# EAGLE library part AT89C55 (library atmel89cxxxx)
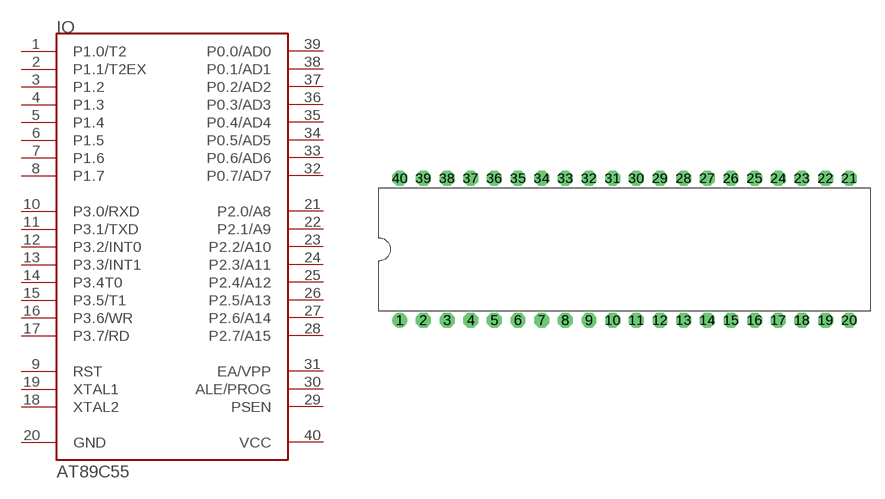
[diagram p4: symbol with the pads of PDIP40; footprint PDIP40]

Designator prefix IO

## AT89C55  [PDIP40]
1  P1.0/T2
2  P1.1/T2EX
3  P1.2
4  P1.3
5  P1.4
6  P1.5
7  P1.6
8  P1.7
9  RST
10  P3.0/RXD
11  P3.1/TXD
12  P3.2/INT0
13  P3.3/INT1
14  P3.4T0
15  P3.5/T1
16  P3.6/WR
17  P3.7/RD
18  XTAL2
19  XTAL1
20  GND  pwr
21  P2.0/A8
22  P2.1/A9
23  P2.2/A10
24  P2.3/A11
25  P2.4/A12
26  P2.5/A13
27  P2.6/A14
28  P2.7/A15
29  PSEN
30  ALE/PROG
31  EA/VPP
32  P0.7/AD7
33  P0.6/AD6
34  P0.5/AD5
35  P0.4/AD4
36  P0.3/AD3
37  P0.2/AD2
38  P0.1/AD1
39  P0.0/AD0
40  VCC  pwr

## Footprint PDIP40 (pad centres in mm)
drill 0.813 pad 1.6 round: 1 -19.05,-7.62
drill 0.813 pad 1.6 octagon: 2 -16.51,-7.62; 3 -13.97,-7.62; 4 -11.43,-7.62; 5 -8.89,-7.62; 6 -6.35,-7.62; 7 -3.81,-7.62; 8 -1.27,-7.62; 9 1.27,-7.62; 10 3.81,-7.62; 11 6.35,-7.62; 12 8.89,-7.62; 13 11.43,-7.62; 14 13.97,-7.62; 15 16.51,-7.62; 16 19.05,-7.62; 17 21.59,-7.62; 18 24.13,-7.62; 19 26.67,-7.62; 20 29.21,-7.62; 21 29.21,7.62; 22 26.67,7.62; 23 24.13,7.62; 24 21.59,7.62; 25 19.05,7.62; 26 16.51,7.62; 27 13.97,7.62; 28 11.43,7.62; 29 8.89,7.62; 30 6.35,7.62; 31 3.81,7.62; 32 1.27,7.62; 33 -1.27,7.62; 34 -3.81,7.62; 35 -6.35,7.62; 36 -8.89,7.62; 37 -11.43,7.62; 38 -13.97,7.62; 39 -16.51,7.62; 40 -19.05,7.62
